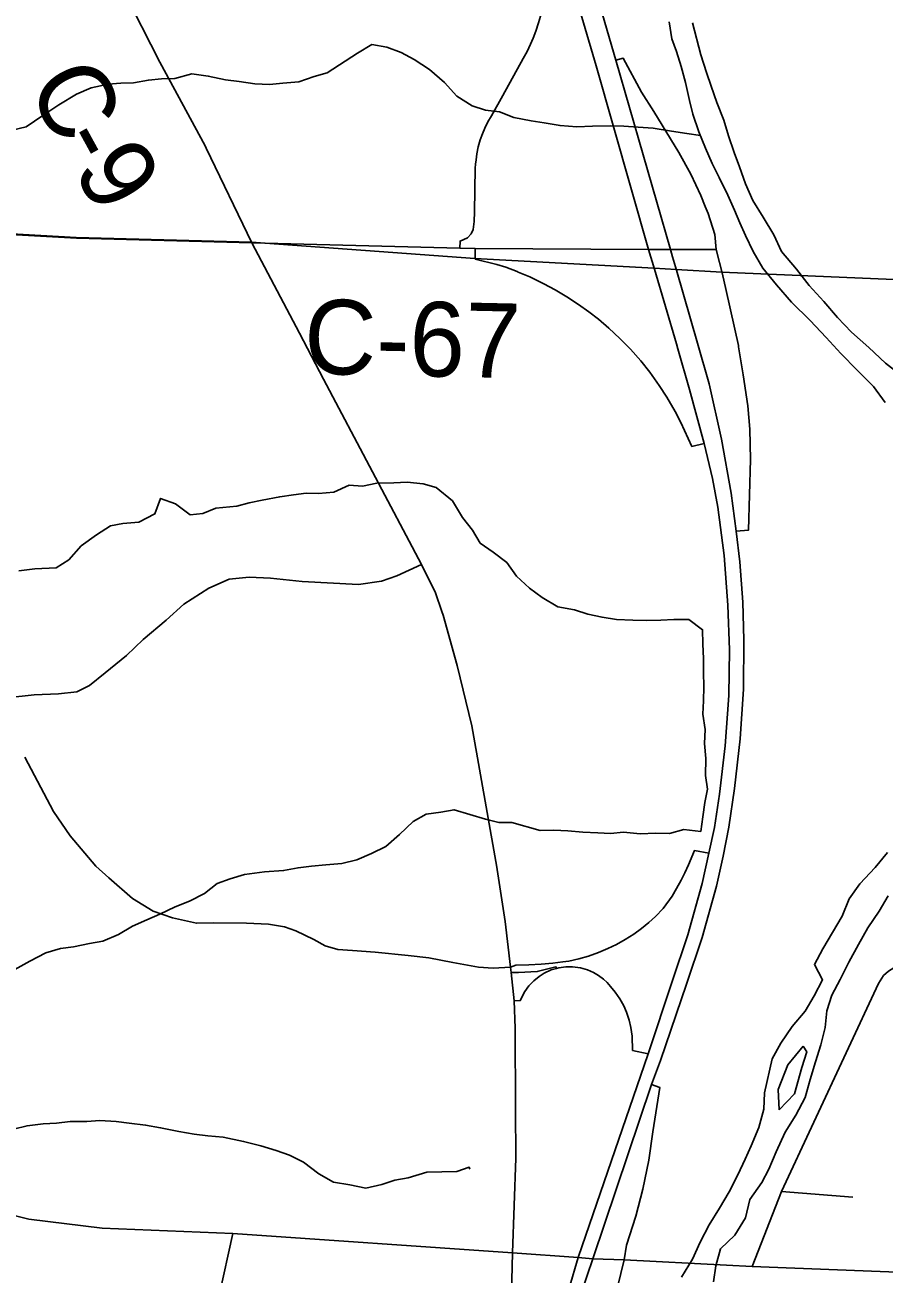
# Model space of a CAD drawing. Extents: x 0 to 34, y 0 to 22.
# Drawn here: x 13.566 to 14.22, y 17.201 to 18.152 of the extents above; entities that cross this region are included whole.
import ezdxf

# ---------------------------------------------------------------- set-up
doc = ezdxf.new("R2010")
doc.units = 0
for name, color, linetype in [('GM_X_City_Street', 7, 'Continuous'), ('GM_X_Corporation', 7, 'Continuous'), ('GM_X_County_Road', 7, 'Continuous'), ('GM_X_County_Road_Text', 7, 'Continuous'), ('GM_X_Interchange_Ramps', 7, 'Continuous'), ('GM_X_Major_River', 7, 'Continuous'), ('GM_X_Minor_River', 7, 'Continuous'), ('GM_X_State_Route', 7, 'Continuous')]:
    doc.layers.add(name, color=color, linetype=linetype)

msp = doc.modelspace()

# ---------------------------------------------------------------- linework, layer by layer
at = {"layer": 'GM_X_City_Street'}
msp.add_line((14.14159, 17.26363), (14.1959, 17.2592), dxfattribs=at)
for points in [[(13.55193, 17.63966), (13.5726, 17.64177), (13.59116, 17.64262), (13.60508, 17.6443), (13.61478, 17.64894), (13.62659, 17.65865), (13.64304, 17.67173), (13.65569, 17.68397), (13.67299, 17.69874), (13.68649, 17.71097), (13.70547, 17.72321), (13.72108, 17.72996), (13.73631, 17.73155), (13.75254, 17.73086), (13.7767, 17.72809), (13.8195, 17.72602), (13.8371, 17.72844), (13.84884, 17.73258), (13.86747, 17.74121)], [(13.56543, 17.59451), (13.58736, 17.55315), (13.60002, 17.53459), (13.61946, 17.51152), (13.62954, 17.50252), (13.64751, 17.48665), (13.66329, 17.4772), (13.67805, 17.47209), (13.69619, 17.46791), (13.70897, 17.46834), (13.73438, 17.46795), (13.75094, 17.46718), (13.76326, 17.46526), (13.77173, 17.46217), (13.7856, 17.45563), (13.79407, 17.45061), (13.8037, 17.44792), (13.81486, 17.44715), (13.83219, 17.446), (13.8573, 17.44333), (13.873, 17.4416), (13.89146, 17.43798), (13.9108, 17.43453), (13.92201, 17.43384), (13.9353, 17.43453)], [(14.11912, 17.20654), (14.14159, 17.26363), (14.21531, 17.42199), (14.21912, 17.42806), (14.22292, 17.43146), (14.23512, 17.43917)], [(13.70989, 17.09827), (13.70187, 17.10614), (13.69764, 17.11216), (13.68841, 17.12609), (13.69478, 17.13148), (13.7004, 17.13647), (13.70561, 17.14413), (13.70851, 17.15479), (13.71105, 17.16468), (13.71117, 17.16598), (13.71206, 17.17607), (13.71348, 17.18443), (13.72392, 17.23153)]]:
    msp.add_lwpolyline(points, dxfattribs=at)
at = {"layer": 'GM_X_Corporation'}
for points in [[(13.37729, 18.33687), (13.36351, 18.00465), (13.41624, 18.00086), (13.60452, 17.99017), (13.738, 17.98662), (13.90817, 17.97425), (14.04454, 17.96674), (14.06138, 17.96581), (14.09613, 17.9639), (14.69725, 17.93806)], [(14.69725, 17.93806), (14.09613, 17.9639), (14.06138, 17.96581), (14.04454, 17.96674), (13.90817, 17.97425), (13.738, 17.98662), (13.60452, 17.99017), (13.41624, 18.00086), (13.36351, 18.00465), (13.33515, 17.28961), (13.33208, 17.22628), (13.31634, 16.90151), (13.31341, 16.8411), (13.31291, 16.83074), (13.30872, 16.74429), (13.30598, 16.68771), (13.29135, 16.39001), (13.26866, 15.91752), (13.25595, 15.61631), (13.25244, 15.53924), (13.23535, 15.27211), (13.23108, 15.20009), (13.22795, 15.1396), (13.21472, 14.94956)]]:
    msp.add_lwpolyline(points, dxfattribs=at)
at = {"layer": 'GM_X_County_Road'}
for p, q in [((13.73822, 17.98608), (13.70362, 18.05824)), ((13.73822, 17.98608), (13.74813, 17.98583)), ((13.74813, 17.98583), (13.79769, 17.98456)), ((14.06398, 17.98103), (14.07785, 17.98102)), ((14.07785, 17.98102), (14.09171, 17.98102)), ((14.02184, 17.21158), (14.09967, 17.20755))]:
    msp.add_line(p, q, dxfattribs=at)
for points in [[(13.70362, 18.05824), (13.70275, 18.06004), (13.66826, 18.12378), (13.6407, 18.17836), (13.6338, 18.19269), (13.62792, 18.21164), (13.61887, 18.25221), (13.61777, 18.26841), (13.6183, 18.28667), (13.61947, 18.30331), (13.62275, 18.34024), (13.62854, 18.4916), (13.63173, 18.54493), (13.63562, 18.60631), (13.6405, 18.65196), (13.64933, 18.71941), (13.65106, 18.73007)], [(13.47687, 17.9969), (13.60474, 17.98963), (13.73822, 17.98608)], [(13.79292, 17.88241), (13.77453, 17.91724), (13.73822, 17.98608)], [(13.79769, 17.98456), (13.8968, 17.98203), (13.90842, 17.98177), (14.04038, 17.98112), (14.05705, 17.98103), (14.06398, 17.98103)], [(13.88307, 17.70537), (13.87817, 17.71946), (13.86747, 17.74121), (13.79292, 17.88241)], [(13.92456, 17.5122), (13.92411, 17.51507), (13.90569, 17.61817), (13.89475, 17.66424), (13.88405, 17.70255), (13.88307, 17.70537)], [(13.93681, 17.21699), (13.93943, 17.28902), (13.93904, 17.32652), (13.93875, 17.3881), (13.93806, 17.40881), (13.93564, 17.43039), (13.9353, 17.43453), (13.93123, 17.46917), (13.92456, 17.5122)], [(13.36901, 17.2849), (13.38023, 17.28351), (13.41069, 17.27741), (13.48798, 17.26251), (13.56851, 17.24267), (13.62428, 17.2356), (13.72392, 17.23153), (13.93681, 17.21699)], [(13.93028, 17.07742), (13.93213, 17.09737), (13.93558, 17.16496), (13.93681, 17.21699)], [(13.93681, 17.21699), (13.98664, 17.21329), (13.99805, 17.21244), (14.02184, 17.21158)], [(14.09967, 17.20755), (14.11912, 17.20654), (14.24906, 17.20149)]]:
    msp.add_lwpolyline(points, dxfattribs=at)
at = {"layer": 'GM_X_Interchange_Ramps'}
msp.add_line((14.10871, 17.90795), (14.09938, 17.94977), dxfattribs=at)
for points in [[(13.96116, 18.21648), (13.96192, 18.20259), (13.96221, 18.19759), (13.9623, 18.19216), (13.96215, 18.18619), (13.96175, 18.18039), (13.96123, 18.17557), (13.96039, 18.16995), (13.95934, 18.16444), (13.95798, 18.1587), (13.95659, 18.15374), (13.95452, 18.14742), (13.95251, 18.14214), (13.95049, 18.13741), (13.94783, 18.13183), (13.945, 18.12653), (13.92933, 18.09832)], [(14.08356, 18.01383), (14.08006, 18.02231), (14.07256, 18.03836), (14.0634, 18.0549), (14.04433, 18.08624), (14.03504, 18.10092), (14.02098, 18.12681), (14.01552, 18.12523)], [(13.92933, 18.09832), (13.92074, 18.08285), (13.9181, 18.0783), (13.91577, 18.0736), (13.91388, 18.06913), (13.91227, 18.06455), (13.91075, 18.05917), (13.90963, 18.05383), (13.90899, 18.04949), (13.90866, 18.04614), (13.90847, 18.04299), (13.90778, 18.00969), (13.9076, 18.00228), (13.90679, 17.99629), (13.9054, 17.99309), (13.9026, 17.98989), (13.89681, 17.9875), (13.8968, 17.98203)], [(14.09171, 17.98102), (14.09081, 17.99246), (14.08575, 18.00853), (14.08356, 18.01383)], [(13.90842, 17.98177), (13.90839, 17.97371), (13.9248, 17.96974), (13.93162, 17.96751), (13.94023, 17.96428), (13.9412, 17.96386)], [(14.09938, 17.94977), (14.09635, 17.96336), (14.09446, 17.97127), (14.09171, 17.98102)], [(13.9412, 17.96386), (13.94998, 17.96015), (13.96063, 17.95503), (13.96927, 17.95038), (13.97814, 17.94511), (13.98709, 17.93924), (13.99485, 17.93365), (14.00214, 17.92797), (14.01009, 17.9212), (14.0185, 17.91335), (14.02651, 17.90511), (14.03438, 17.89616), (14.0412, 17.88761), (14.04852, 17.87745), (14.0542, 17.86869), (14.06056, 17.85774), (14.06499, 17.8492), (14.07339, 17.83113), (14.0828, 17.83337)], [(14.10699, 17.76664), (14.11651, 17.76739), (14.11799, 17.82114), (14.11753, 17.84418), (14.11595, 17.86207), (14.11233, 17.88553), (14.10894, 17.9069), (14.10871, 17.90795)], [(14.08623, 17.52122), (14.07528, 17.52331), (14.07075, 17.51243), (14.06795, 17.50632), (14.06511, 17.50066), (14.06164, 17.4943), (14.0582, 17.48849), (14.05157, 17.4791), (14.04552, 17.47298), (14.04064, 17.46858), (14.03486, 17.46389), (14.02909, 17.45972), (14.02265, 17.45559), (14.01599, 17.45183), (14.00938, 17.44859), (14.00213, 17.44553), (13.99461, 17.44288), (13.98737, 17.44079), (13.97969, 17.43906), (13.97508, 17.43856), (13.96757, 17.43749), (13.95859, 17.43688), (13.9492, 17.43628), (13.93936, 17.43606), (13.9353, 17.43453)], [(13.93564, 17.43039), (13.94134, 17.43039), (13.95566, 17.43108), (13.96988, 17.43478), (13.97025, 17.43348)], [(13.93806, 17.40881), (13.94273, 17.40906), (13.94619, 17.41585), (13.94932, 17.42024), (13.95302, 17.42417), (13.95703, 17.42743), (13.96096, 17.4299), (13.96633, 17.43236), (13.97025, 17.43348), (13.97203, 17.43399), (13.97732, 17.43473), (13.98243, 17.43476), (13.98854, 17.43394), (13.99395, 17.43237), (13.99836, 17.43044), (14.00224, 17.42817), (14.00603, 17.42531), (14.00882, 17.42268), (14.01136, 17.41979), (14.01489, 17.41541), (14.01837, 17.41045), (14.02148, 17.40492), (14.02361, 17.40015), (14.02564, 17.39416), (14.02697, 17.38851), (14.02784, 17.38199), (14.02817, 17.37107), (14.03994, 17.36856)], [(14.02184, 17.21158), (14.02349, 17.22276), (14.03068, 17.24482), (14.03606, 17.26548), (14.04066, 17.28742), (14.0437, 17.30902), (14.04904, 17.34279), (14.04252, 17.34503)], [(13.98089, 17.07627), (13.98581, 17.0898), (13.99914, 17.12763), (14.00743, 17.15105), (14.01031, 17.16438), (14.01932, 17.20113), (14.02184, 17.21158)]]:
    msp.add_lwpolyline(points, dxfattribs=at)
at = {"layer": 'GM_X_Major_River'}
for points in [[(14.05602, 18.15438), (14.05803, 18.14143), (14.06163, 18.13187), (14.06519, 18.12041), (14.06836, 18.10819), (14.07149, 18.09446), (14.07394, 18.08416), (14.07859, 18.07078), (14.08365, 18.05815), (14.08872, 18.04666), (14.09419, 18.03592), (14.10074, 18.0225), (14.10582, 18.01101), (14.1098, 18.00144), (14.11415, 17.99186), (14.11997, 17.9796), (14.1273, 17.96693), (14.13765, 17.95419), (14.14914, 17.94106), (14.16326, 17.92711), (14.17551, 17.91396), (14.18664, 17.90197), (14.19927, 17.8892), (14.21153, 17.87681), (14.22038, 17.86448)], [(14.23218, 17.88552), (14.22061, 17.89448), (14.20796, 17.9065), (14.19493, 17.91814), (14.18416, 17.92936), (14.17379, 17.94134), (14.16266, 17.95371), (14.15306, 17.96605), (14.14158, 17.97956), (14.13577, 17.9922), (14.1277, 18.00565), (14.11962, 18.01834), (14.11418, 18.03098), (14.10952, 18.04398), (14.10557, 18.05507), (14.10128, 18.06768), (14.09773, 18.07952), (14.09231, 18.09292), (14.08802, 18.10553), (14.08443, 18.11586), (14.08016, 18.12923), (14.07382, 18.15366)], [(14.22218, 17.52193), (14.21284, 17.51035), (14.20122, 17.49804), (14.19303, 17.48643), (14.18783, 17.47324), (14.17293, 17.44847), (14.16662, 17.43645), (14.17283, 17.42493), (14.16652, 17.41253), (14.15945, 17.40089), (14.14974, 17.38931), (14.14115, 17.37657), (14.13446, 17.36455), (14.12863, 17.33885), (14.128, 17.32633), (14.12431, 17.31235), (14.11834, 17.29842), (14.11397, 17.28825), (14.10842, 17.27621), (14.10172, 17.26343), (14.09426, 17.25105), (14.08642, 17.23829), (14.07971, 17.22514), (14.07376, 17.21196), (14.06553, 17.19846)], [(14.08972, 17.19494), (14.09148, 17.20706), (14.09515, 17.2199), (14.10598, 17.23032), (14.1142, 17.24345), (14.11752, 17.25743), (14.1265, 17.27054), (14.13201, 17.28069), (14.13759, 17.29387), (14.14433, 17.30892), (14.15255, 17.32167), (14.15965, 17.3352), (14.16333, 17.3488), (14.1674, 17.36239), (14.17145, 17.37522), (14.17475, 17.38844), (14.17614, 17.40133), (14.17979, 17.41303), (14.1861, 17.42505), (14.19281, 17.43821), (14.20029, 17.45174), (14.20737, 17.46451), (14.21597, 17.47725), (14.22265, 17.48889)], [(14.15816, 17.37434), (14.1465, 17.36014), (14.13892, 17.3413), (14.13974, 17.32572)], [(14.13974, 17.32572), (14.15136, 17.33802), (14.15708, 17.35803), (14.16073, 17.37011), (14.15816, 17.37434)]]:
    msp.add_lwpolyline(points, dxfattribs=at)
at = {"layer": 'GM_X_Minor_River'}
for points in [[(14.07979, 18.0678), (14.06955, 18.06939), (14.05783, 18.07109), (14.04384, 18.07358), (14.03247, 18.07412), (14.02149, 18.07505), (14.01126, 18.0752), (13.99761, 18.07502), (13.98585, 18.07444), (13.97298, 18.07539), (13.96088, 18.07747), (13.95105, 18.07913), (13.93781, 18.08161), (13.92688, 18.08595), (13.91628, 18.08725), (13.90609, 18.09044), (13.89444, 18.09783), (13.88511, 18.10824), (13.8735, 18.11829), (13.86185, 18.12568), (13.85207, 18.13115), (13.84113, 18.13511), (13.82979, 18.13718), (13.8187, 18.1305), (13.79576, 18.11564), (13.78586, 18.11275), (13.77406, 18.10874), (13.76191, 18.10778), (13.75167, 18.10679), (13.74068, 18.10734), (13.72858, 18.10904), (13.71836, 18.11033), (13.70513, 18.11318), (13.69265, 18.11489), (13.67971, 18.11128), (13.66947, 18.11105), (13.6596, 18.11006), (13.6482, 18.10795), (13.63872, 18.10771), (13.62886, 18.1071), (13.61594, 18.10425), (13.60488, 18.09947), (13.5915, 18.09131), (13.57926, 18.08313), (13.56663, 18.07457), (13.55599, 18.07207)], [(14.08391, 17.59333), (14.08293, 17.60475), (14.08346, 17.61538), (14.08172, 17.62719), (14.08224, 17.63745), (14.08238, 17.64809), (14.08216, 17.65911), (14.0823, 17.66937), (14.08169, 17.68078), (14.08146, 17.69143), (14.07095, 17.69918), (14.05958, 17.69935), (14.04972, 17.69874), (14.0391, 17.69852), (14.02849, 17.69868), (14.01599, 17.69924), (14.00502, 17.70093), (13.99406, 17.70337), (13.98387, 17.70656), (13.9714, 17.70903), (13.95937, 17.71604), (13.9496, 17.72303), (13.93988, 17.7323), (13.93244, 17.74267), (13.92193, 17.75043), (13.91217, 17.75741), (13.90624, 17.76738), (13.89879, 17.777), (13.891, 17.78965), (13.87863, 17.79972), (13.86882, 17.80253), (13.8567, 17.80385), (13.84646, 17.80324), (13.83357, 17.80305), (13.82255, 17.80093), (13.81232, 17.80146), (13.80088, 17.79631), (13.78912, 17.79535), (13.77964, 17.79549), (13.77015, 17.79411), (13.75952, 17.79275), (13.74622, 17.79028), (13.73634, 17.78815), (13.72682, 17.78563), (13.71088, 17.78397), (13.70097, 17.77993), (13.69148, 17.77893), (13.68023, 17.78746), (13.66891, 17.79143), (13.66458, 17.77971), (13.65237, 17.77343), (13.64023, 17.77247), (13.63073, 17.77072), (13.62002, 17.76365), (13.60853, 17.75546), (13.59891, 17.74459), (13.58935, 17.73865), (13.57304, 17.73775), (13.56089, 17.73641)], [(13.5579, 17.43279), (13.56936, 17.43909), (13.58157, 17.44536), (13.59261, 17.44862), (13.60248, 17.44999), (13.61465, 17.45247), (13.6249, 17.45422), (13.63672, 17.45936), (13.64742, 17.46567), (13.65848, 17.47044), (13.66839, 17.47486), (13.67984, 17.48039), (13.69089, 17.48478), (13.70234, 17.49069), (13.71192, 17.49815), (13.72182, 17.5018), (13.73286, 17.50506), (13.74805, 17.50711), (13.76247, 17.50804), (13.77349, 17.51016), (13.78374, 17.51152), (13.79475, 17.5125), (13.80689, 17.51346), (13.8183, 17.51633), (13.82935, 17.52111), (13.84042, 17.52626), (13.85078, 17.53561), (13.86114, 17.54534), (13.87108, 17.55089), (13.88209, 17.55263), (13.89235, 17.55438), (13.91613, 17.54718), (13.92633, 17.54475), (13.93618, 17.5446), (13.95771, 17.53858), (13.96832, 17.5388), (13.97893, 17.53827), (13.99029, 17.53734), (14.00165, 17.53679), (14.0115, 17.53626), (14.02137, 17.53725), (14.03386, 17.53593), (14.04599, 17.53651), (14.05623, 17.53636), (14.06726, 17.53923), (14.08013, 17.5379), (14.08179, 17.5489), (14.08308, 17.5599), (14.08511, 17.57013), (14.08374, 17.58042), (14.08391, 17.59333)], [(13.55701, 17.3112), (13.56728, 17.3137), (13.57942, 17.31504), (13.58967, 17.31565), (13.59992, 17.31702), (13.6128, 17.31682), (13.62267, 17.31782), (13.63517, 17.31687), (13.64501, 17.31559), (13.6575, 17.31426), (13.66884, 17.31219), (13.68282, 17.30932), (13.69455, 17.30725), (13.70476, 17.30596), (13.7165, 17.30502), (13.732, 17.30175), (13.74522, 17.29851), (13.75692, 17.29492), (13.7671, 17.29135), (13.77764, 17.28587), (13.78927, 17.27696), (13.80056, 17.27071), (13.81304, 17.26862), (13.82513, 17.26616), (13.8373, 17.26902), (13.8472, 17.27229), (13.85746, 17.27404), (13.87154, 17.27839), (13.89429, 17.27881), (13.90381, 17.28209), (13.90417, 17.28057)]]:
    msp.add_lwpolyline(points, dxfattribs=at)
at = {"layer": 'GM_X_State_Route'}
for points in [[(14.05865, 17.97547), (14.05705, 17.98103), (14.01552, 18.12523), (13.98664, 18.22383), (13.94321, 18.37275), (13.89847, 18.52716), (13.87566, 18.60568), (13.86974, 18.6309), (13.8625, 18.66665), (13.85987, 18.68453)], [(14.06153, 17.90915), (14.04476, 17.96621), (14.04038, 17.98112), (14.00049, 18.1209), (13.97161, 18.21949)], [(14.07766, 17.90975), (14.0616, 17.96528), (14.05865, 17.97547)], [(13.98927, 17.18684), (13.99805, 17.21244), (14.04252, 17.34503), (14.04937, 17.3634), (14.06933, 17.42152), (14.08117, 17.45706), (14.09214, 17.4961), (14.09718, 17.51913), (14.10157, 17.54106), (14.10574, 17.57067), (14.11012, 17.60839), (14.11254, 17.64612), (14.11298, 17.68384), (14.1121, 17.71235), (14.1099, 17.74328), (14.10699, 17.76664), (14.10333, 17.79548), (14.09587, 17.83649), (14.08644, 17.87882), (14.07766, 17.90975)], [(14.0828, 17.83337), (14.07141, 17.87449), (14.06263, 17.90541), (14.06153, 17.90915)], [(13.9799, 17.18997), (13.98664, 17.21329), (14.03994, 17.36856), (14.05838, 17.42362), (14.07022, 17.45915), (14.08119, 17.49819), (14.08623, 17.52122), (14.0906, 17.54095), (14.09433, 17.56617), (14.09872, 17.60302), (14.10157, 17.6414), (14.10201, 17.67606), (14.10069, 17.71027), (14.09784, 17.748), (14.09302, 17.78484), (14.08907, 17.80678), (14.0828, 17.83337)]]:
    msp.add_lwpolyline(points, dxfattribs=at)

# ---------------------------------------------------------------- texts
at = {"layer": 'GM_X_County_Road_Text'}
for s, height, rotation, p in [('C', 0.05682, 298.06285, (13.56658, 18.10605)), ('-', 0.05682, 298.71302, (13.58887, 18.06425)), ('9', 0.05682, 301.24453, (13.60145, 18.04142)), ('C-67', 0.056818, 358.775, (13.77766, 17.88652))]:
    msp.add_text(s, height=height, rotation=rotation, dxfattribs=at).set_placement(p)

doc.saveas('drawing.dxf')
